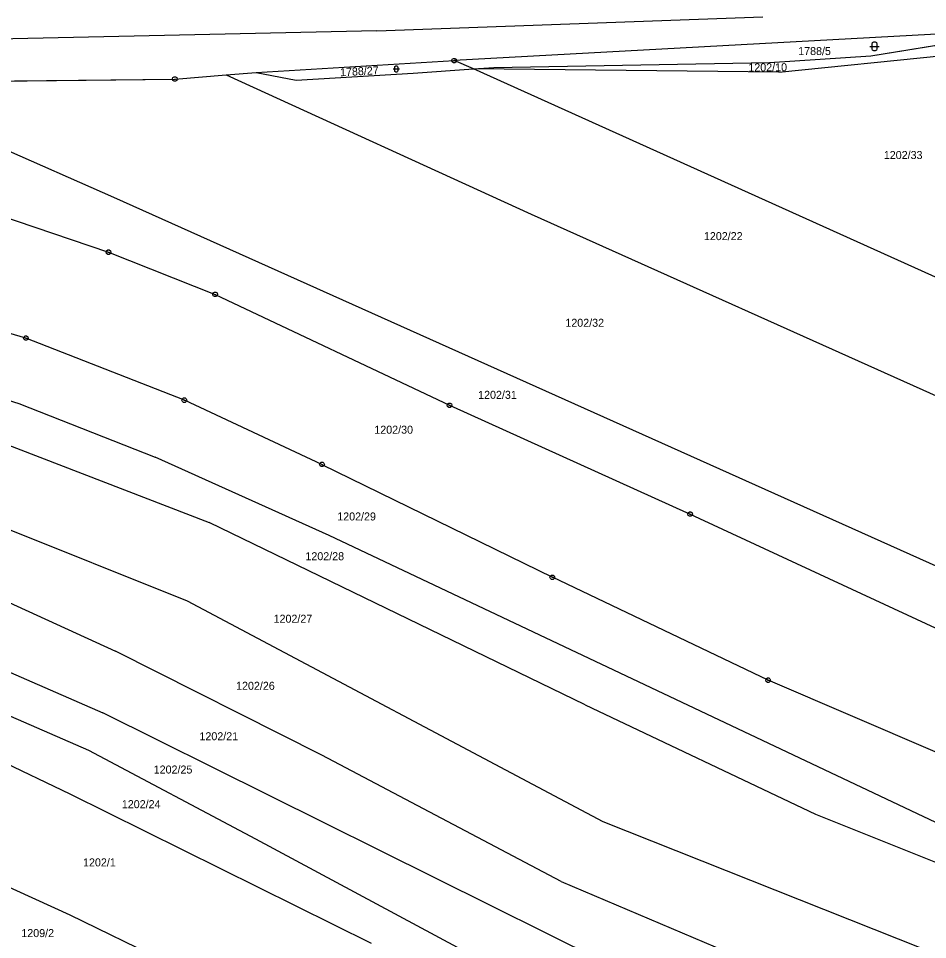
# Model space of a CAD drawing. Extents: x -777309 to -774195, y -1144706 to -1143600.
# Drawn here: x -776362 to -776168.9, y -1144044.3 to -1143848.6 of the extents above; entities that cross this region are included whole.
import ezdxf

# ---------------------------------------------------------------- set-up
doc = ezdxf.new("R2010")
doc.units = 0
for name, color, linetype in [('1', 7, 'Continuous'), ('11', 7, 'Continuous'), ('2', 7, 'Continuous'), ('3', 7, 'Continuous'), ('4', 7, 'Continuous'), ('8', 7, 'Continuous')]:
    doc.layers.add(name, color=color, linetype=linetype)

msp = doc.modelspace()

# ---------------------------------------------------------------- linework, layer by layer
at = {"layer": '1'}
for p, q in [((-776144.62, -1143850.73), (-776269.47, -1143857.59)), ((-776180.94, -1143856.57), (-776144.62, -1143850.73)), ((-776311.57, -1143860.13), (-776269.47, -1143857.59)), ((-776265.4, -1143859.37), (-776269.47, -1143857.59)), ((-776261.07, -1143859.06), (-776202.5, -1143858)), ((-776202.5, -1143858), (-776180.94, -1143856.57)), ((-776200.5, -1143860.05), (-776165.57, -1143856.47)), ((-776317.92, -1143860.64), (-776311.57, -1143860.13)), ((-776311.57, -1143860.13), (-776303.07, -1143861.75)), ((-776278.19, -1143860.27), (-776265.4, -1143859.37)), ((-776265.4, -1143859.37), (-776261.07, -1143859.06)), ((-776200.5, -1143860.05), (-776265.4, -1143859.37)), ((-776154.75, -1143909.25), (-776265.4, -1143859.37)), ((-776396.99, -1143862.27), (-776328.8, -1143861.5)), ((-776328.8, -1143861.5), (-776317.92, -1143860.64)), ((-776317.92, -1143860.64), (-776253.1, -1143890.21)), ((-776303.07, -1143861.75), (-776278.19, -1143860.27)), ((-776341.75, -1143886.7), (-776396.99, -1143862.27)), ((-776380.21, -1143885.62), (-776342.91, -1143898.29)), ((-776152.51, -1143971.59), (-776341.75, -1143886.7)), ((-776360.45, -1143916.55), (-776455.73, -1143888.41)), ((-776253.1, -1143890.21), (-776154.06, -1143934.69)), ((-776342.91, -1143898.29), (-776320.26, -1143907.26)), ((-776320.26, -1143907.26), (-776270.48, -1143930.82)), ((-776408.9, -1143915.72), (-776361.98, -1143930.46)), ((-776326.79, -1143929.74), (-776360.45, -1143916.55)), ((-776361.98, -1143930.46), (-776332.97, -1143941.86)), ((-776297.56, -1143943.4), (-776326.79, -1143929.74)), ((-776383.3, -1143931.9), (-776321.54, -1143955.7)), ((-776270.48, -1143930.82), (-776219.35, -1143953.95)), ((-776296.05, -1143958.5), (-776332.97, -1143941.86)), ((-776297.56, -1143943.4), (-776248.62, -1143967.36)), ((-776378, -1143951.65), (-776326.2, -1143972.4)), ((-776219.35, -1143953.95), (-776159.54, -1143981.75)), ((-776241.68, -1143994.5), (-776321.54, -1143955.7)), ((-776167.18, -1144019.46), (-776296.05, -1143958.5)), ((-776381.58, -1143964.67), (-776341.39, -1143983.08)), ((-776202.79, -1143989.23), (-776248.62, -1143967.36)), ((-776326.2, -1143972.4), (-776237.87, -1144019.26)), ((-776390.42, -1143976.01), (-776344.1, -1143996.17)), ((-776297.59, -1144005.18), (-776341.39, -1143983.08)), ((-776382.3, -1143988.84), (-776347.15, -1144004.12)), ((-776167.32, -1144004.47), (-776202.79, -1143989.23)), ((-776241.68, -1143994.5), (-776192.7, -1144017.69)), ((-776221.27, -1144057.17), (-776344.1, -1143996.17)), ((-776382, -1143998.69), (-776351.09, -1144013.34)), ((-776347.15, -1144004.12), (-776311.69, -1144022.93)), ((-776246.74, -1144031.99), (-776297.59, -1144005.18)), ((-776351.09, -1144013.34), (-776287.1, -1144045.07)), ((-776398.64, -1144017.46), (-776351.09, -1144039.08)), ((-776192.7, -1144017.69), (-776162.43, -1144029.85)), ((-776237.87, -1144019.26), (-776170, -1144046.22)), ((-776311.69, -1144022.93), (-776268.85, -1144045.98)), ((-776246.74, -1144031.99), (-776181.26, -1144059.74)), ((-776351.09, -1144039.08), (-776262.34, -1144082.22))]:
    msp.add_line(p, q, dxfattribs=at)
at = {"layer": '11'}
msp.add_lwpolyline([(-776396.99, -1143862.27), (-776328.8, -1143861.5), (-776317.92, -1143860.64), (-776311.57, -1143860.13), (-776303.07, -1143861.75), (-776278.19, -1143860.27), (-776265.4, -1143859.37), (-776261.07, -1143859.06), (-776202.5, -1143858), (-776180.94, -1143856.57), (-776144.62, -1143850.73), (-776130.99, -1143849.3), (-776128.41, -1143848.96), (-776109.31, -1143852.26)], dxfattribs=at)
at = {"layer": '3'}
for points in [[(-776180.68, -1143854.06), (-776180.58, -1143853.77), (-776180.33, -1143853.59), (-776180.02, -1143853.59), (-776179.77, -1143853.77), (-776179.67, -1143854.06), (-776179.67, -1143855.06), (-776179.77, -1143855.35), (-776180.02, -1143855.53), (-776180.33, -1143855.53), (-776180.58, -1143855.35), (-776180.68, -1143855.06)], [(-776282.11, -1143859.04), (-776282.05, -1143858.84), (-776281.88, -1143858.72), (-776281.67, -1143858.72), (-776281.51, -1143858.84), (-776281.44, -1143859.04), (-776281.44, -1143859.71), (-776281.51, -1143859.9), (-776281.67, -1143860.02), (-776281.88, -1143860.02), (-776282.05, -1143859.9), (-776282.11, -1143859.71)]]:
    msp.add_lwpolyline(points, close=True, dxfattribs=at)
for points in [[(-776181.18, -1143854.56), (-776179.91, -1143854.56), (-776179.18, -1143854.56)], [(-776282.45, -1143859.37), (-776281.6, -1143859.37), (-776281.11, -1143859.37)]]:
    msp.add_lwpolyline(points, dxfattribs=at)
at = {"layer": '4'}
for q in [(-776203.92, -1143848.29), (-776430.3, -1143854.43)]:
    msp.add_line((-776285.88, -1143851.28), q, dxfattribs=at)
at = {"layer": '8'}
for p, q in [((-776269.59, -1143857.59), (-776269.35, -1143857.59)), ((-776328.92, -1143861.5), (-776328.68, -1143861.5)), ((-776343.03, -1143898.29), (-776342.79, -1143898.29)), ((-776320.38, -1143907.26), (-776320.14, -1143907.26)), ((-776360.57, -1143916.55), (-776360.33, -1143916.55)), ((-776326.91, -1143929.74), (-776326.67, -1143929.74)), ((-776270.6, -1143930.82), (-776270.36, -1143930.82)), ((-776297.68, -1143943.4), (-776297.44, -1143943.4)), ((-776219.47, -1143953.95), (-776219.23, -1143953.95)), ((-776248.74, -1143967.36), (-776248.5, -1143967.36)), ((-776202.91, -1143989.23), (-776202.67, -1143989.23))]:
    msp.add_line(p, q, dxfattribs=at)
for points in [[(-776269.32, -1143857.11), (-776269.07, -1143857.29), (-776268.97, -1143857.58), (-776269.07, -1143857.87), (-776269.32, -1143858.05), (-776269.63, -1143858.05), (-776269.88, -1143857.87), (-776269.98, -1143857.58), (-776269.88, -1143857.29), (-776269.63, -1143857.11)], [(-776328.65, -1143861.02), (-776328.4, -1143861.2), (-776328.3, -1143861.49), (-776328.4, -1143861.78), (-776328.65, -1143861.96), (-776328.96, -1143861.96), (-776329.21, -1143861.78), (-776329.31, -1143861.49), (-776329.21, -1143861.2), (-776328.96, -1143861.02)], [(-776342.76, -1143897.81), (-776342.51, -1143897.99), (-776342.41, -1143898.28), (-776342.51, -1143898.57), (-776342.76, -1143898.75), (-776343.07, -1143898.75), (-776343.32, -1143898.57), (-776343.42, -1143898.28), (-776343.32, -1143897.99), (-776343.07, -1143897.81)], [(-776320.11, -1143906.78), (-776319.86, -1143906.96), (-776319.76, -1143907.25), (-776319.86, -1143907.54), (-776320.11, -1143907.72), (-776320.42, -1143907.72), (-776320.67, -1143907.54), (-776320.77, -1143907.25), (-776320.67, -1143906.96), (-776320.42, -1143906.78)], [(-776360.3, -1143916.07), (-776360.05, -1143916.25), (-776359.95, -1143916.54), (-776360.05, -1143916.83), (-776360.3, -1143917.01), (-776360.61, -1143917.01), (-776360.86, -1143916.83), (-776360.96, -1143916.54), (-776360.86, -1143916.25), (-776360.61, -1143916.07)], [(-776326.64, -1143929.26), (-776326.39, -1143929.44), (-776326.29, -1143929.73), (-776326.39, -1143930.02), (-776326.64, -1143930.2), (-776326.95, -1143930.2), (-776327.2, -1143930.02), (-776327.3, -1143929.73), (-776327.2, -1143929.44), (-776326.95, -1143929.26)], [(-776270.33, -1143930.34), (-776270.08, -1143930.52), (-776269.98, -1143930.81), (-776270.08, -1143931.1), (-776270.33, -1143931.28), (-776270.64, -1143931.28), (-776270.89, -1143931.1), (-776270.99, -1143930.81), (-776270.89, -1143930.52), (-776270.64, -1143930.34)], [(-776297.41, -1143942.92), (-776297.16, -1143943.1), (-776297.06, -1143943.39), (-776297.16, -1143943.68), (-776297.41, -1143943.86), (-776297.72, -1143943.86), (-776297.97, -1143943.68), (-776298.07, -1143943.39), (-776297.97, -1143943.1), (-776297.72, -1143942.92)], [(-776219.2, -1143953.47), (-776218.95, -1143953.65), (-776218.85, -1143953.94), (-776218.95, -1143954.23), (-776219.2, -1143954.41), (-776219.51, -1143954.41), (-776219.76, -1143954.23), (-776219.86, -1143953.94), (-776219.76, -1143953.65), (-776219.51, -1143953.47)], [(-776248.47, -1143966.88), (-776248.22, -1143967.06), (-776248.12, -1143967.35), (-776248.22, -1143967.64), (-776248.47, -1143967.82), (-776248.78, -1143967.82), (-776249.03, -1143967.64), (-776249.13, -1143967.35), (-776249.03, -1143967.06), (-776248.78, -1143966.88)], [(-776202.64, -1143988.75), (-776202.39, -1143988.93), (-776202.29, -1143989.22), (-776202.39, -1143989.51), (-776202.64, -1143989.69), (-776202.95, -1143989.69), (-776203.2, -1143989.51), (-776203.3, -1143989.22), (-776203.2, -1143988.93), (-776202.95, -1143988.75)]]:
    msp.add_lwpolyline(points, close=True, dxfattribs=at)

# ---------------------------------------------------------------- texts
at = {"layer": '2'}
for s, p in [('1788/5', (-776196.4, -1143856.41)), ('1202/33', (-776178.21, -1143878.5)), ('1202/22', (-776216.43, -1143895.73)), ('1202/32', (-776245.86, -1143914.14)), ('1202/31', (-776264.39, -1143929.45)), ('1202/30', (-776286.44, -1143936.86)), ('1202/29', (-776294.32, -1143955.29)), ('1202/28', (-776301.08, -1143963.74)), ('1202/27', (-776307.84, -1143977.02)), ('1202/26', (-776315.81, -1143991.27)), ('1202/21', (-776323.59, -1144001.99)), ('1202/25', (-776333.31, -1144009.06)), ('1202/24', (-776340.08, -1144016.42)), ('1202/1', (-776348.32, -1144028.79)), ('1209/2', (-776361.43, -1144043.81))]:
    msp.add_text(s, height=1.7, dxfattribs=at).set_placement(p)
for s, rotation, p in [('1202/10', 0.4011, (-776206.98, -1143859.89)), ('1788/27', 3.0367, (-776293.68, -1143860.92))]:
    msp.add_text(s, height=1.7, rotation=rotation, dxfattribs=at).set_placement(p)

doc.saveas('drawing.dxf')
